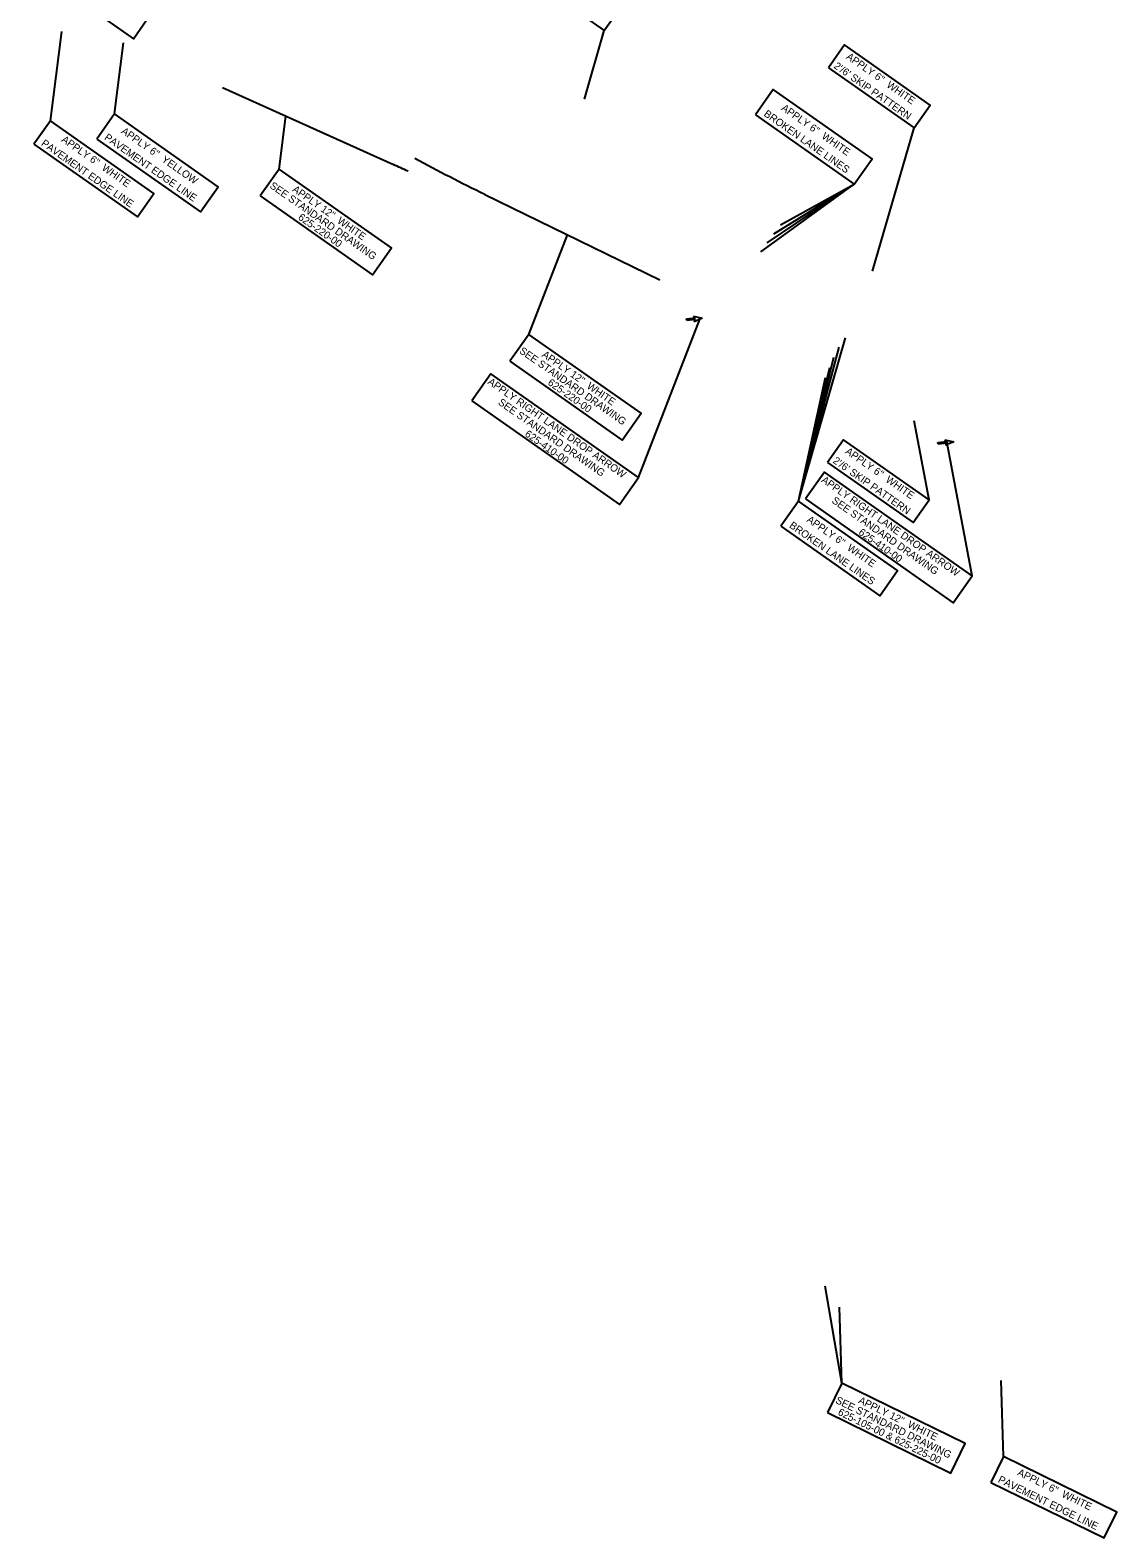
# Model space of a CAD drawing. Extents: x 1966013 to 1974896, y 789499 to 804826.
# Drawn here: x 1971752 to 1972929, y 793439 to 795072 of the extents above; entities that cross this region are included whole.
import ezdxf

# ---------------------------------------------------------------- set-up
doc = ezdxf.new("R2010")
doc.units = 0
doc.layers.add('RD_EX_H2O_BlueLn', color=7, linetype='Continuous')
doc.layers.add('RD_PD_Final_LnLine', color=7, linetype='Continuous')

msp = doc.modelspace()

# ---------------------------------------------------------------- linework, layer by layer
at = {"layer": 'RD_EX_H2O_BlueLn'}
for p, q in [((1971774.3, 794973.8), (1971786.5, 795070.5)), ((1972352.3, 794997.1), (1972373.8, 795071.4)), ((1971843.5, 794981.3), (1971853.2, 795058.1)), ((1972021.9, 794921.5), (1972029.1, 794978.8)), ((1972664.4, 794811), (1972709.3, 794966.1)), ((1972543.3, 794831.7), (1972644.5, 794905.2)), ((1972550.3, 794841.6), (1972644.5, 794905.2)), ((1972557.4, 794851.4), (1972644.5, 794905.2)), ((1972564.7, 794861.1), (1972644.5, 794905.2)), ((1972292.2, 794742.5), (1972334.1, 794850.3)), ((1972410.9, 794587.4), (1972477.8, 794759.5)), ((1972462.9, 794759.2), (1972472.5, 794760.2)), ((1972463.1, 794757.4), (1972462.9, 794759.2)), ((1972472.7, 794758.4), (1972463.1, 794757.4)), ((1972470.6, 794762.1), (1972479.9, 794760.1)), ((1972472.5, 794760.2), (1972470.6, 794762.1)), ((1972479.9, 794760.1), (1972471.2, 794756.2)), ((1972471.2, 794756.2), (1972472.7, 794758.4)), ((1972584.3, 794561.9), (1972634.9, 794738.6)), ((1972584.3, 794561.9), (1972628.2, 794728.5)), ((1972584.3, 794561.9), (1972622.6, 794717.9)), ((1972584.3, 794561.9), (1972618.2, 794706.7)), ((1972584.3, 794561.9), (1972613.4, 794695.7)), ((1972725.6, 794563.3), (1972709.5, 794648.7)), ((1972735.1, 794625.2), (1972744.7, 794626.3)), ((1972735.3, 794623.4), (1972735.1, 794625.2)), ((1972744.9, 794624.5), (1972735.3, 794623.4)), ((1972742.8, 794628.2), (1972752.2, 794626.2)), ((1972744.7, 794626.3), (1972742.8, 794628.2)), ((1972752.2, 794626.2), (1972743.5, 794622.3)), ((1972743.5, 794622.3), (1972744.9, 794624.5)), ((1972772.2, 794480.9), (1972744.7, 794626.3)), ((1972631.2, 793606.6), (1972613, 793711.6)), ((1972631.2, 793606.6), (1972628.6, 793688.8)), ((1972806.1, 793527.2), (1972803.5, 793609.4))]:
    msp.add_line(p, q, dxfattribs=at)
for points in [[(1971752.3, 795141.1), (1971864.1, 795062.5), (1971882, 795088), (1971770.2, 795166.6)], [(1972262, 795150), (1972373.8, 795071.4), (1972391.8, 795096.9), (1972279.9, 795175.5)], [(1972616.6, 795031.2), (1972709.3, 794966.1), (1972726.6, 794990.8), (1972633.9, 795055.9)], [(1972537.5, 794980.4), (1972644.5, 794905.2), (1972663.8, 794932.6), (1972556.7, 795007.8)], [(1971824.3, 794953.9), (1971936.7, 794875), (1971955.9, 794902.4), (1971843.5, 794981.3)], [(1971756.4, 794948.3), (1971868.3, 794869.7), (1971886.2, 794895.2), (1971774.3, 794973.8)], [(1972001.4, 794892.4), (1972123, 794807), (1972143.4, 794836.1), (1972021.9, 794921.5)], [(1972271.7, 794713.4), (1972393.3, 794628), (1972413.7, 794657.1), (1972292.2, 794742.5)], [(1972230.5, 794670.6), (1972390.5, 794558.3), (1972410.9, 794587.4), (1972251, 794699.7)], [(1972615.6, 794603.7), (1972708.3, 794538.6), (1972725.6, 794563.3), (1972632.9, 794628.4)], [(1972591.8, 794564.2), (1972751.7, 794451.8), (1972772.2, 794480.9), (1972612.2, 794593.2)], [(1972565.1, 794534.6), (1972672.1, 794459.4), (1972691.4, 794486.8), (1972584.3, 794561.9)], [(1972615.6, 793574.7), (1972749, 793509.3), (1972764.7, 793541.3), (1972631.2, 793606.6)], [(1972792.4, 793499.2), (1972915.2, 793439.1), (1972928.9, 793467.1), (1972806.1, 793527.2)]]:
    msp.add_lwpolyline(points, close=True, dxfattribs=at)
at = {"layer": 'RD_PD_Final_LnLine'}
for p, q in [((1971960.4, 795009.8), (1972145.5, 794926.3)), ((1972244.6, 794894.1), (1972433.9, 794801.5))]:
    msp.add_line(p, q, dxfattribs=at)
for centre, radius, start, end in [((1973117.1, 796676), 1984, 241.4466, 243.9112), ((1969914, 789980.4), 5426, 65.5302, 65.7151)]:
    msp.add_arc(centre, radius, start, end, dxfattribs=at)

# ---------------------------------------------------------------- texts
at = {"layer": 'RD_EX_H2O_BlueLn'}
for s, height, rotation, p in [("APPLY 6''  WHITE", 7.999, 324.9238, (1972635.1, 795041.6)), ("2'/6' SKIP PATTERN", 7.999, 324.9238, (1972621.7, 795031.5)), ('BROKEN LANE LINES', 8, 324.9236, (1972545.9, 794979.7)), ("APPLY 6''  WHITE", 8, 324.9236, (1972564.8, 794986)), ("APPLY 6''  YELLOW", 8, 324.9236, (1971850.1, 794960.9)), ('PAVEMENT EDGE LINE', 8, 324.9236, (1971763.5, 794947.7)), ("APPLY 6''  WHITE", 8, 324.9236, (1971785.4, 794951.8)), ('PAVEMENT EDGE LINE', 8, 324.9236, (1971831.9, 794954.1)), ('SEE STANDARD DRAWING', 8, 324.9236, (1972010.9, 794901.8)), ("APPLY 12''  WHITE", 8, 324.9236, (1972035.4, 794897.9)), (' 625-220-00', 8, 324.9236, (1972039.2, 794869.3)), ('SEE STANDARD DRAWING', 8, 324.9236, (1972281.2, 794722.9)), ("APPLY 12''  WHITE", 8, 324.9236, (1972305.7, 794718.9)), ('APPLY RIGHT LANE DROP ARROW', 8, 324.9236, (1972247, 794689.5)), (' 625-220-00', 8, 324.9236, (1972309.5, 794690.3)), ('SEE STANDARD DRAWING', 8, 324.9236, (1972258.2, 794667.2)), ('625-410-00 ', 7.999, 324.9236, (1972287.1, 794632.9)), ("2'/6' SKIP PATTERN", 7.999, 324.9238, (1972620.7, 794604)), ("APPLY 6''  WHITE", 7.999, 324.9238, (1972634.1, 794614.1)), ('APPLY RIGHT LANE DROP ARROW', 8, 324.9236, (1972608.2, 794583.1)), ('SEE STANDARD DRAWING', 8, 324.9236, (1972619.5, 794560.8)), ('BROKEN LANE LINES', 8, 324.9236, (1972573.5, 794533.9)), ("APPLY 6''  WHITE", 8, 324.9236, (1972592.4, 794540.2)), ('625-410-00 ', 7.999, 324.9236, (1972648.4, 794526.4)), ('SEE STANDARD DRAWING', 8, 333.9112, (1972623.5, 793585.5)), ('625-105-00 & 625-225-00', 8, 333.9112, (1972626.1, 793572.7)), ("APPLY 12''  WHITE", 8, 333.9112, (1972648.3, 793585.4)), ("APPLY 6''  WHITE", 8, 333.9112, (1972820.5, 793507.3)), ('PAVEMENT EDGE LINE', 8, 333.9112, (1972799.5, 793499.7))]:
    msp.add_text(s, height=height, rotation=rotation, dxfattribs=at).set_placement(p)

doc.saveas('drawing.dxf')
